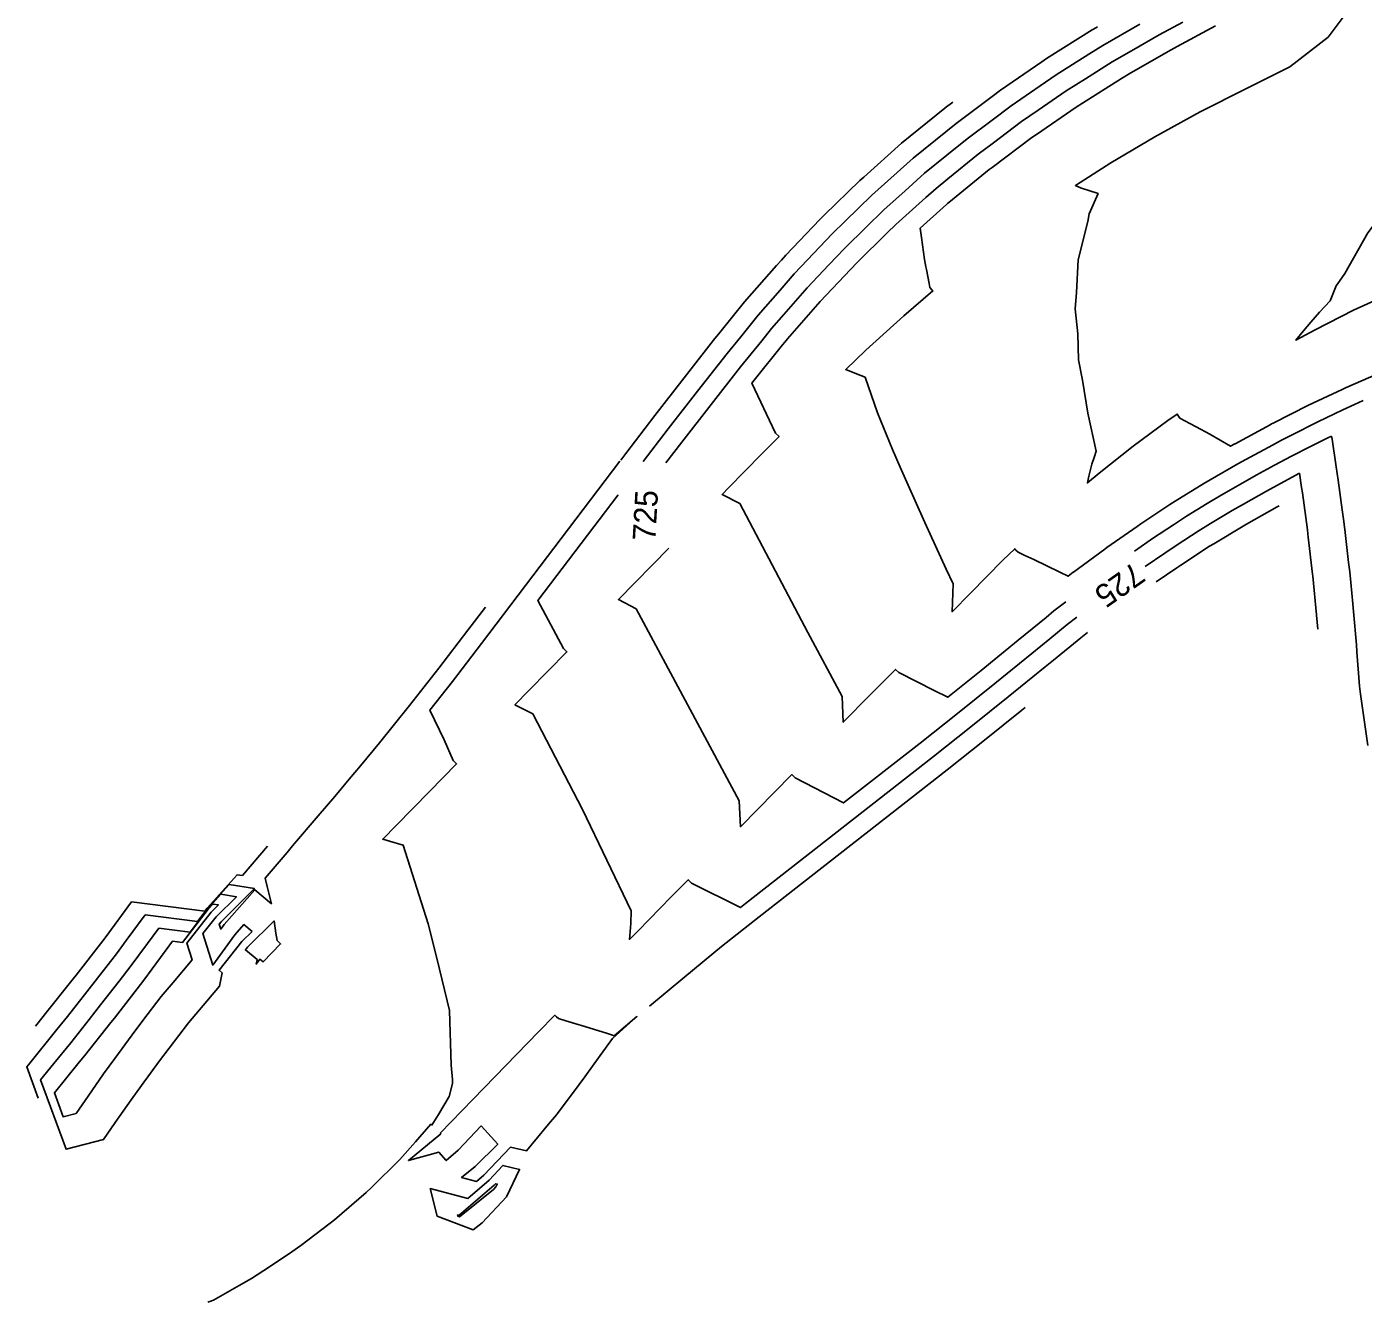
# Model space of a CAD drawing. Extents: x 1487507 to 1489130, y 497211 to 499439.
# Drawn here: x 1488426.5 to 1488567.6, y 499130.9 to 499265.5 of the extents above; entities that cross this region are included whole.
import ezdxf

# ---------------------------------------------------------------- set-up
doc = ezdxf.new("R2010")
doc.units = 0
for name, color, linetype in [('Prop CMT Ditch DDE', 7, 'Continuous'), ('Prop Drainage Ditch Flow Line', 7, 'Continuous'), ('Prop Drainage Structure Box Number Symbol CELL', 7, 'Continuous')]:
    doc.layers.add(name, color=color, linetype=linetype)

msp = doc.modelspace()

# ---------------------------------------------------------------- linework, layer by layer
at = {"layer": 'Prop CMT Ditch DDE'}
for points in [[(1488569.25, 499228.96), (1488565.77, 499227.45), (1488565.39, 499227.27), (1488561.84, 499225.59), (1488558.12, 499223.7), (1488557.96, 499223.62), (1488557.81, 499223.54), (1488554.11, 499221.54), (1488554.09, 499221.53), (1488553.63, 499221.26), (1488551.42, 499222.55), (1488549.98, 499223.32), (1488549.34, 499223.68), (1488548.27, 499224.25), (1488548.06, 499224.55), (1488547.99, 499224.66), (1488547.01, 499223.99), (1488543.33, 499221.27), (1488539.75, 499218.44), (1488538.51, 499217.39), (1488538.67, 499218.12), (1488538.99, 499219.37), (1488539.25, 499220.19), (1488539.43, 499220.74), (1488538.55, 499224.76), (1488537.99, 499228.26), (1488537.56, 499230.38), (1488537.49, 499233.12), (1488537.21, 499235.79), (1488537.37, 499237.5), (1488537.52, 499240.94), (1488538.55, 499244.99), (1488538.71, 499245.81), (1488539.64, 499247.94), (1488537.8, 499248.54), (1488537.24, 499248.78), (1488540.97, 499251.17), (1488545.64, 499253.94), (1488550.4, 499256.56), (1488555.25, 499259.01), (1488559.87, 499261.3), (1488563.92, 499264.44), (1488567.3, 499268.99)], [(1488548.57, 499266.04), (1488546.1, 499264.71), (1488543.43, 499263.16), (1488541.13, 499261.83), (1488538.32, 499260.06), (1488536.28, 499258.77), (1488533.33, 499256.74), (1488531.56, 499255.53), (1488528.44, 499253.19), (1488526.97, 499252.1), (1488523.78, 499249.5), (1488522.54, 499248.49), (1488521.45, 499247.51), (1488518.29, 499244.66), (1488517.39, 499243.79), (1488514.21, 499240.68), (1488513.5, 499239.94), (1488510.3, 499236.54), (1488506.85, 499232.59), (1488506.57, 499232.26), (1488506.34, 499231.99), (1488503.32, 499228.24), (1488503.08, 499227.93), (1488505.6, 499222.65), (1488505.96, 499222.3), (1488504.12, 499220.44), (1488500.61, 499216.87), (1488499.94, 499216.19), (1488501.81, 499215.24), (1488508.99, 499201.61), (1488512.62, 499194.86), (1488512.74, 499192.13), (1488515.63, 499195.07), (1488518.24, 499197.72), (1488518.6, 499197.37), (1488522.35, 499195.47), (1488523.77, 499194.78), (1488527.3, 499197.61), (1488531.2, 499200.79), (1488534.15, 499203.2), (1488534.98, 499203.88), (1488536.24, 499204.86)], [(1488539.57, 499265.55), (1488539.15, 499265.31), (1488539.01, 499265.22), (1488534.18, 499262.18), (1488533.7, 499261.85), (1488529.35, 499258.86), (1488528.46, 499258.19), (1488524.65, 499255.35), (1488523.56, 499254.46), (1488520.11, 499251.67), (1488517.09, 499248.96), (1488515.76, 499247.76), (1488512.95, 499245.03), (1488511.57, 499243.69), (1488508.95, 499240.93), (1488507.57, 499239.46), (1488506.07, 499237.75), (1488503.74, 499235.09), (1488501.91, 499232.83), (1488500.47, 499231.05), (1488497.36, 499227.09), (1488494.27, 499223.12), (1488491.63, 499219.66)], [(1488552.03, 499265.63), (1488547.99, 499263.46), (1488547.03, 499262.95), (1488542.93, 499260.57), (1488542.12, 499260.1), (1488537.98, 499257.48), (1488537.33, 499257.07), (1488533.15, 499254.19), (1488532.66, 499253.86), (1488528.44, 499250.69), (1488528.13, 499250.47), (1488523.89, 499247.01), (1488523.75, 499246.9), (1488523.63, 499246.79), (1488520.87, 499244.3), (1488520.98, 499243.31), (1488521.31, 499240.97), (1488521.45, 499240.2), (1488521.51, 499239.92), (1488521.8, 499238.45), (1488521.89, 499238.04), (1488522.13, 499237.75), (1488522.21, 499237.66), (1488519.14, 499235.05), (1488515.11, 499231.41), (1488513, 499229.37), (1488514.12, 499228.91), (1488515.04, 499228.55), (1488516.34, 499224.81), (1488517.93, 499220.91), (1488518.74, 499219.05), (1488519.45, 499217.47), (1488521.34, 499213.22), (1488523.6, 499208.28), (1488524.33, 499206.75), (1488524.23, 499203.8), (1488526.16, 499205.76), (1488529.6, 499209.25), (1488530.84, 499210.45), (1488530.96, 499210.31), (1488531.19, 499210.09), (1488531.91, 499209.73), (1488532.86, 499209.3), (1488535.59, 499207.96), (1488536.47, 499207.55), (1488537, 499207.96), (1488537.04, 499207.99), (1488540.34, 499210.42), (1488540.56, 499210.59), (1488543.75, 499212.81), (1488544.14, 499213.08), (1488547.22, 499215.13), (1488547.76, 499215.48), (1488550.79, 499217.32), (1488551.47, 499217.73), (1488554.39, 499219.4), (1488555.22, 499219.87), (1488558.04, 499221.4), (1488559.01, 499221.91), (1488560.06, 499222.45), (1488562.83, 499223.86), (1488565.47, 499225.11), (1488566.71, 499225.68), (1488567.63, 499226.09)], [(1488581.78, 499261.19), (1488578.9, 499257.79), (1488578.04, 499256.88), (1488574.86, 499252.95), (1488574.56, 499252.52), (1488571.42, 499248.53), (1488570.06, 499246.38), (1488568.13, 499243.78), (1488565.69, 499239.52), (1488565.12, 499238.7), (1488564.79, 499238.21), (1488564.13, 499236.61), (1488563.02, 499235.42), (1488562.11, 499234.38), (1488561.31, 499233.45), (1488560.52, 499232.45), (1488562.54, 499233.57), (1488566.62, 499235.63), (1488571.03, 499237.63), (1488573.36, 499238.15)], [(1488524.32, 499257.6), (1488523.49, 499256.98), (1488523.45, 499256.94), (1488518.89, 499253.26), (1488514.91, 499249.68), (1488514.49, 499249.31), (1488510.72, 499245.65), (1488510.26, 499245.19), (1488506.68, 499241.43), (1488506.2, 499240.92), (1488505.68, 499240.33), (1488502.32, 499236.5), (1488499.7, 499233.26), (1488499.05, 499232.45), (1488495.93, 499228.5), (1488492.85, 499224.52), (1488489.78, 499220.52), (1488489.24, 499219.8)], [(1488543.48, 499210.2), (1488544.17, 499210.68), (1488545.4, 499211.54), (1488547.6, 499212.99), (1488548.97, 499213.89), (1488551.14, 499215.21), (1488552.63, 499216.1), (1488554.69, 499217.28), (1488556.32, 499218.2), (1488558.27, 499219.26), (1488560.06, 499220.21), (1488562, 499221.19), (1488563.83, 499222.12), (1488564.29, 499222.34)], [(1488564.29, 499222.34), (1488564.35, 499222.03), (1488564.77, 499219.11), (1488565, 499217.68), (1488565.4, 499214.56), (1488565.58, 499213.33), (1488565.73, 499212.18), (1488566.09, 499208.98), (1488566.2, 499208), (1488566.53, 499204.63), (1488566.61, 499203.82), (1488566.91, 499200.3), (1488566.97, 499199.57), (1488567.22, 499195.94), (1488567.33, 499195.11), (1488568.11, 499189.67)], [(1488489.16, 499219.69), (1488474.55, 499200.44), (1488471.48, 499196.44), (1488469.1, 499193.42), (1488470.61, 499190.28), (1488471.57, 499188.09), (1488471.92, 499187.74), (1488469.04, 499184.81), (1488465.53, 499181.24), (1488464.12, 499179.81), (1488464.84, 499179.59), (1488466.29, 499179.16), (1488468.93, 499170.87), (1488469.85, 499167.08), (1488471.17, 499161.7), (1488471.35, 499155.93), (1488471.48, 499154.44), (1488471.47, 499154), (1488471.14, 499152.63), (1488470, 499150.72), (1488469.32, 499149.62), (1488469.21, 499149.72), (1488469.2, 499149.72), (1488467.57, 499147.86), (1488465.92, 499145.99), (1488462.94, 499143.04), (1488462.38, 499142.5), (1488459.02, 499139.62), (1488458.58, 499139.25), (1488455.47, 499136.92), (1488454.54, 499136.23), (1488452.15, 499134.66), (1488450.26, 499133.43), (1488448.98, 499132.69), (1488446.27, 499131.14), (1488445.77, 499130.97), (1488445.66, 499130.91)], [(1488488.96, 499216.15), (1488480.49, 499204.99), (1488483.21, 499199.91), (1488483.57, 499199.56), (1488479.56, 499195.5), (1488478.07, 499193.98), (1488479.95, 499193.04), (1488485.21, 499182.92), (1488490.35, 499172.24), (1488490.31, 499170.88), (1488490.17, 499169.21), (1488491.08, 499170.13), (1488494.58, 499173.69), (1488496.37, 499175.51), (1488496.73, 499175.15), (1488501.9, 499172.57), (1488502.43, 499172.99), (1488522.27, 499188.53), (1488526.22, 499191.66), (1488530.15, 499194.81), (1488534.05, 499197.98), (1488534.92, 499198.69), (1488537.81, 499201.05), (1488538.52, 499201.6), (1488538.52, 499201.61)], [(1488545.77, 499206.94), (1488547.94, 499208.44), (1488548.37, 499208.73), (1488551.4, 499210.71), (1488551.85, 499210.98), (1488554.95, 499212.84), (1488555.29, 499213.04), (1488558.53, 499214.87), (1488558.74, 499214.98)], [(1488474.97, 499204.28), (1488473.12, 499201.84), (1488470.05, 499197.84), (1488466.94, 499193.89), (1488463.79, 499189.98), (1488461.78, 499187.55), (1488460.59, 499186.11), (1488459.07, 499184.31), (1488457.32, 499182.24), (1488454.61, 499179.08), (1488454.03, 499178.4), (1488451.69, 499175.67), (1488451.91, 499174.81), (1488452.37, 499172.98), (1488450.62, 499174.45), (1488447.37, 499170.79), (1488447.01, 499170.31), (1488446.86, 499170.81), (1488447.07, 499171.08), (1488450.58, 499174.58), (1488447.89, 499175.01), (1488445.62, 499172.48), (1488444.56, 499171.1), (1488439.05, 499171.79), (1488437.05, 499169.09), (1488436.01, 499167.69), (1488434.02, 499165.12), (1488432.89, 499163.67), (1488430.83, 499161.07), (1488429.73, 499159.69), (1488426.71, 499155.97), (1488426.54, 499155.75), (1488427.75, 499152.46)], [(1488531.93, 499193.69), (1488531.58, 499193.4), (1488527.65, 499190.25), (1488523.69, 499187.13), (1488503.85, 499171.58), (1488499.9, 499168.45), (1488496, 499165.28), (1488492.27, 499162.18)], [(1488451.96, 499179.05), (1488449.31, 499175.95), (1488448.74, 499176.04), (1488445.58, 499172.52), (1488445.35, 499172.21), (1488437.6, 499173.17), (1488434.8, 499169.39), (1488434.56, 499169.07), (1488431.75, 499165.44), (1488431.44, 499165.04), (1488428.53, 499161.38), (1488428.28, 499161.06), (1488427.46, 499160.05)]]:
    msp.add_lwpolyline(points, dxfattribs=at)
for points in [[(1488450.33, 499170.06), (1488449.47, 499170.78), (1488448.5, 499169.69), (1488446.18, 499166.51), (1488445.14, 499169.82), (1488446.54, 499171.59), (1488448.68, 499173.72), (1488447.04, 499173.98), (1488445.66, 499172.44), (1488443.78, 499169.99), (1488440.49, 499170.4), (1488439.3, 499168.79), (1488437.46, 499166.31), (1488436.28, 499164.79), (1488434.34, 499162.29), (1488433.13, 499160.76), (1488431.19, 499158.31), (1488429.39, 499156.1), (1488427.99, 499154.38), (1488430.69, 499147.06), (1488434.65, 499148.11), (1488435.88, 499149.87), (1488437.56, 499152.29), (1488438.65, 499153.78), (1488440.55, 499156.38), (1488441.59, 499157.74), (1488443.63, 499160.4), (1488444.79, 499161.78), (1488446.88, 499164.27), (1488447.16, 499165.69), (1488446.84, 499165.95), (1488449.24, 499168.98)], [(1488446.19, 499172.95), (1488445.7, 499172.4), (1488442.99, 499168.89), (1488441.93, 499169.02), (1488441.55, 499168.5), (1488438.9, 499164.92), (1488438.55, 499164.47), (1488435.79, 499160.91), (1488435.43, 499160.45), (1488432.64, 499156.94), (1488432.07, 499156.24), (1488429.45, 499153.01), (1488430.38, 499150.49), (1488431.74, 499150.85), (1488433.02, 499152.68), (1488434.65, 499155.03), (1488435.84, 499156.66), (1488437.65, 499159.14), (1488438.81, 499160.65), (1488440.74, 499163.17), (1488442.01, 499164.68), (1488443.99, 499167.04), (1488443.43, 499168.83), (1488446.01, 499172.09), (1488446.78, 499172.85)], [(1488452.98, 499169.09), (1488452.85, 499169.87), (1488452.65, 499171.16), (1488449.85, 499168.4), (1488449.63, 499168.11), (1488450.86, 499167.08), (1488450.77, 499166.61), (1488451.16, 499167.13), (1488451.48, 499166.83), (1488451.48, 499166.83), (1488453.33, 499168.74), (1488453.14, 499168.93)], [(1488470.19, 499148.77), (1488470.19, 499148.77), (1488470.26, 499148.7), (1488466.83, 499145.86), (1488470.03, 499146.77), (1488470.83, 499145.87), (1488472.08, 499146.95), (1488474.52, 499149.53), (1488476.26, 499147.59), (1488473.87, 499145.23), (1488472.45, 499144.07), (1488474.03, 499143.66), (1488474.8, 499144.33), (1488477.59, 499147.28), (1488479.28, 499146.88), (1488481.63, 499149.71), (1488482.45, 499150.7), (1488484.86, 499153.91), (1488485.45, 499154.69), (1488487.09, 499156.96), (1488488.38, 499158.76), (1488490.95, 499161.06), (1488488.56, 499159.02), (1488488.38, 499159.09), (1488487.84, 499159.29), (1488485.47, 499160.01), (1488484.52, 499160.3), (1488483.46, 499160.62), (1488482.66, 499160.86), (1488482.48, 499161.04), (1488482.3, 499161.21), (1488480.58, 499159.46), (1488477.11, 499155.91), (1488473.65, 499152.34)], [(1488469.12, 499142.92), (1488469.88, 499140), (1488473.67, 499138.55), (1488474.6, 499139.3), (1488477.18, 499142.03), (1488478.57, 499144.94), (1488476.81, 499145.35), (1488475.34, 499143.8), (1488473.11, 499141.88)]]:
    msp.add_lwpolyline(points, close=True, dxfattribs=at)
at = {"layer": 'Prop Drainage Ditch Flow Line'}
for points in [[(1488494.02, 499219.53), (1488495.7, 499221.71), (1488498.78, 499225.69), (1488501.9, 499229.64), (1488504.13, 499232.41), (1488505.15, 499233.68), (1488506.46, 499235.17), (1488508.93, 499238), (1488511.23, 499240.43), (1488512.89, 499242.18), (1488515.17, 499244.41), (1488517.02, 499246.21), (1488519.27, 499248.24), (1488521.32, 499250.08), (1488523.67, 499251.98), (1488525.81, 499253.72), (1488528.45, 499255.69), (1488530.45, 499257.19), (1488533.52, 499259.3), (1488535.23, 499260.48), (1488538.66, 499262.64), (1488540.14, 499263.57), (1488544.04, 499265.83)], [(1488560.92, 499218.41), (1488558.51, 499217.12), (1488557.43, 499216.54), (1488554.99, 499215.16), (1488553.79, 499214.47), (1488551.5, 499213.1), (1488550.19, 499212.3), (1488547.99, 499210.86), (1488546.67, 499209.99), (1488544.62, 499208.57)], [(1488562.83, 499201.97), (1488562.71, 499203.44), (1488562.71, 499203.47), (1488562.3, 499207.56), (1488562.28, 499207.75), (1488561.83, 499211.68), (1488561.79, 499212.04), (1488561.73, 499212.43), (1488561.23, 499216.34), (1488561.13, 499216.93), (1488560.92, 499218.41)], [(1488537.38, 499203.23), (1488536.39, 499202.46), (1488534.53, 499200.95), (1488532.63, 499199.38), (1488528.73, 499196.21), (1488524.8, 499193.06), (1488520.84, 499189.94), (1488512.78, 499183.62), (1488507.67, 499186.26), (1488507.31, 499186.62), (1488501.88, 499181.1), (1488501.76, 499183.83), (1488490.86, 499204.12), (1488489, 499205.08), (1488494.33, 499210.5)]]:
    msp.add_lwpolyline(points, dxfattribs=at)
msp.add_lwpolyline([(1488472, 499140.15), (1488472.04, 499140.01), (1488472.23, 499139.94), (1488475.81, 499142.83), (1488476.07, 499143.1), (1488476.2, 499143.38), (1488476.03, 499143.42), (1488475.88, 499143.27), (1488472.2, 499140.1)], close=True, dxfattribs=at)

# ---------------------------------------------------------------- texts
at = {"layer": 'Prop Drainage Structure Box Number Symbol CELL'}
for rotation, p in [(86.7878, (1488492.89, 499211.23)), (215.1001, (1488543.43, 499209.14))]:
    msp.add_text('725', height=2.4, rotation=rotation, dxfattribs=at).set_placement(p)

doc.saveas('drawing.dxf')
